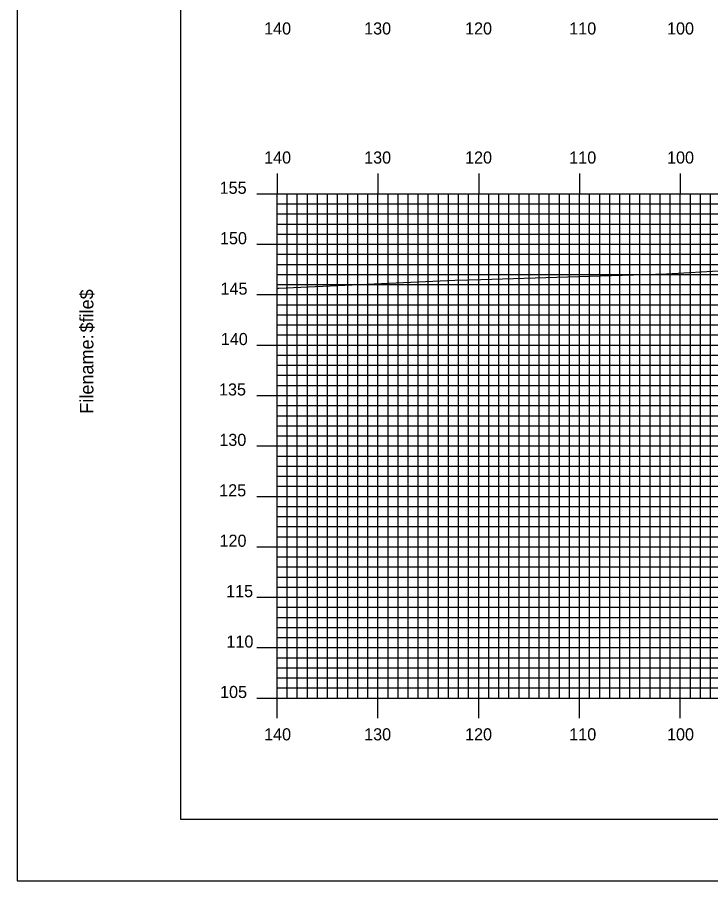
# Model space of a CAD drawing. Extents: x 1769661 to 1770005, y 442591 to 442811.
# Drawn here: x 1769661.2 to 1769730, y 442590.5 to 442676.2 of the extents above; entities that cross this region are included whole.
import ezdxf

# ---------------------------------------------------------------- set-up
doc = ezdxf.new("R2010")
doc.units = 0
for name, color, linetype in [('BORDER', 7, 'Continuous'), ('H_V ANNOTATION', 7, 'Continuous'), ('MAJOR', 7, 'Continuous'), ('MINOR', 7, 'Continuous'), ('PLOT BOUNDARY', 7, 'Continuous'), ('S_Roadway_Centerline', 7, 'Continuous')]:
    doc.layers.add(name, color=color, linetype=linetype)

msp = doc.modelspace()

# ---------------------------------------------------------------- linework, layer by layer
at = {"layer": 'BORDER'}
msp.add_lwpolyline([(1769677.415, 442596.665), (1769997.415, 442596.665), (1769997.415, 442806.665), (1769677.415, 442806.665)], close=True, dxfattribs=at)
at = {"layer": 'MAJOR'}
for p, q in [((1769687.015, 442660.669), (1769687.015, 442658.665)), ((1769697.015, 442660.669), (1769697.015, 442658.665)), ((1769707.015, 442660.669), (1769707.015, 442658.665)), ((1769717.015, 442660.669), (1769717.015, 442658.665)), ((1769727.015, 442660.669), (1769727.015, 442658.665)), ((1769685.011, 442658.665), (1769687.015, 442658.665)), ((1769687.015, 442658.665), (1769967.015, 442658.665)), ((1769687.015, 442608.665), (1769687.015, 442658.665)), ((1769687.015, 442608.665), (1769687.015, 442658.665)), ((1769687.015, 442658.665), (1769967.015, 442658.665)), ((1769697.015, 442608.665), (1769697.015, 442658.665)), ((1769707.015, 442608.665), (1769707.015, 442658.665)), ((1769717.015, 442608.665), (1769717.015, 442658.665)), ((1769727.015, 442608.665), (1769727.015, 442658.665)), ((1769685.011, 442653.665), (1769687.015, 442653.665)), ((1769687.015, 442653.665), (1769967.015, 442653.665)), ((1769685.011, 442648.665), (1769687.015, 442648.665)), ((1769687.015, 442648.665), (1769967.015, 442648.665)), ((1769685.011, 442643.665), (1769687.015, 442643.665)), ((1769687.015, 442643.665), (1769967.015, 442643.665)), ((1769685.011, 442638.665), (1769687.015, 442638.665)), ((1769687.015, 442638.665), (1769967.015, 442638.665)), ((1769685.011, 442633.665), (1769687.015, 442633.665)), ((1769687.015, 442633.665), (1769967.015, 442633.665)), ((1769685.011, 442628.665), (1769687.015, 442628.665)), ((1769687.015, 442628.665), (1769967.015, 442628.665)), ((1769685.011, 442623.665), (1769687.015, 442623.665)), ((1769687.015, 442623.665), (1769967.015, 442623.665)), ((1769685.011, 442618.665), (1769687.015, 442618.665)), ((1769687.015, 442618.665), (1769967.015, 442618.665)), ((1769685.011, 442613.665), (1769687.015, 442613.665)), ((1769687.015, 442613.665), (1769967.015, 442613.665)), ((1769685.011, 442608.665), (1769687.015, 442608.665)), ((1769687.015, 442608.665), (1769967.015, 442608.665)), ((1769687.015, 442608.665), (1769967.015, 442608.665)), ((1769687.015, 442606.661), (1769687.015, 442608.665)), ((1769697.015, 442606.661), (1769697.015, 442608.665)), ((1769707.015, 442606.661), (1769707.015, 442608.665)), ((1769717.015, 442606.661), (1769717.015, 442608.665)), ((1769727.015, 442606.661), (1769727.015, 442608.665))]:
    msp.add_line(p, q, dxfattribs=at)
at = {"layer": 'MINOR'}
for p, q in [((1769688.015, 442608.665), (1769688.015, 442658.665)), ((1769689.015, 442608.665), (1769689.015, 442658.665)), ((1769690.015, 442608.665), (1769690.015, 442658.665)), ((1769691.015, 442608.665), (1769691.015, 442658.665)), ((1769692.015, 442608.665), (1769692.015, 442658.665)), ((1769693.015, 442608.665), (1769693.015, 442658.665)), ((1769694.015, 442608.665), (1769694.015, 442658.665)), ((1769695.015, 442608.665), (1769695.015, 442658.665)), ((1769696.015, 442608.665), (1769696.015, 442658.665)), ((1769698.015, 442608.665), (1769698.015, 442658.665)), ((1769699.015, 442608.665), (1769699.015, 442658.665)), ((1769700.015, 442608.665), (1769700.015, 442658.665)), ((1769701.015, 442608.665), (1769701.015, 442658.665)), ((1769702.015, 442608.665), (1769702.015, 442658.665)), ((1769703.015, 442608.665), (1769703.015, 442658.665)), ((1769704.015, 442608.665), (1769704.015, 442658.665)), ((1769705.015, 442608.665), (1769705.015, 442658.665)), ((1769706.015, 442608.665), (1769706.015, 442658.665)), ((1769708.015, 442608.665), (1769708.015, 442658.665)), ((1769709.015, 442608.665), (1769709.015, 442658.665)), ((1769710.015, 442608.665), (1769710.015, 442658.665)), ((1769711.015, 442608.665), (1769711.015, 442658.665)), ((1769712.015, 442608.665), (1769712.015, 442658.665)), ((1769713.015, 442608.665), (1769713.015, 442658.665)), ((1769714.015, 442608.665), (1769714.015, 442658.665)), ((1769715.015, 442608.665), (1769715.015, 442658.665)), ((1769716.015, 442608.665), (1769716.015, 442658.665)), ((1769718.015, 442608.665), (1769718.015, 442658.665)), ((1769719.015, 442608.665), (1769719.015, 442658.665)), ((1769720.015, 442608.665), (1769720.015, 442658.665)), ((1769721.015, 442608.665), (1769721.015, 442658.665)), ((1769722.015, 442608.665), (1769722.015, 442658.665)), ((1769723.015, 442608.665), (1769723.015, 442658.665)), ((1769724.015, 442608.665), (1769724.015, 442658.665)), ((1769725.015, 442608.665), (1769725.015, 442658.665)), ((1769726.015, 442608.665), (1769726.015, 442658.665)), ((1769728.015, 442608.665), (1769728.015, 442658.665)), ((1769729.015, 442608.665), (1769729.015, 442658.665)), ((1769730.015, 442608.665), (1769730.015, 442658.665)), ((1769687.015, 442657.665), (1769967.015, 442657.665)), ((1769687.015, 442657.665), (1769689.019, 442657.665)), ((1769687.015, 442656.665), (1769967.015, 442656.665)), ((1769687.015, 442656.665), (1769689.019, 442656.665)), ((1769687.015, 442655.665), (1769967.015, 442655.665)), ((1769687.015, 442655.665), (1769689.019, 442655.665)), ((1769687.015, 442654.665), (1769967.015, 442654.665)), ((1769687.015, 442654.665), (1769689.019, 442654.665)), ((1769687.015, 442652.665), (1769967.015, 442652.665)), ((1769687.015, 442652.665), (1769689.019, 442652.665)), ((1769687.015, 442651.665), (1769967.015, 442651.665)), ((1769687.015, 442651.665), (1769689.019, 442651.665)), ((1769687.015, 442650.665), (1769967.015, 442650.665)), ((1769687.015, 442650.665), (1769689.019, 442650.665)), ((1769687.015, 442649.665), (1769967.015, 442649.665)), ((1769687.015, 442649.665), (1769689.019, 442649.665)), ((1769687.015, 442647.665), (1769967.015, 442647.665)), ((1769687.015, 442647.665), (1769689.019, 442647.665)), ((1769687.015, 442646.665), (1769967.015, 442646.665)), ((1769687.015, 442646.665), (1769689.019, 442646.665)), ((1769687.015, 442645.665), (1769967.015, 442645.665)), ((1769687.015, 442645.665), (1769689.019, 442645.665)), ((1769687.015, 442644.665), (1769967.015, 442644.665)), ((1769687.015, 442644.665), (1769689.019, 442644.665)), ((1769687.015, 442642.665), (1769967.015, 442642.665)), ((1769687.015, 442642.665), (1769689.019, 442642.665)), ((1769687.015, 442641.665), (1769967.015, 442641.665)), ((1769687.015, 442641.665), (1769689.019, 442641.665)), ((1769687.015, 442640.665), (1769967.015, 442640.665)), ((1769687.015, 442640.665), (1769689.019, 442640.665)), ((1769687.015, 442639.665), (1769967.015, 442639.665)), ((1769687.015, 442639.665), (1769689.019, 442639.665)), ((1769687.015, 442637.665), (1769967.015, 442637.665)), ((1769687.015, 442637.665), (1769689.019, 442637.665)), ((1769687.015, 442636.665), (1769967.015, 442636.665)), ((1769687.015, 442636.665), (1769689.019, 442636.665)), ((1769687.015, 442635.665), (1769967.015, 442635.665)), ((1769687.015, 442635.665), (1769689.019, 442635.665)), ((1769687.015, 442634.665), (1769967.015, 442634.665)), ((1769687.015, 442634.665), (1769689.019, 442634.665)), ((1769687.015, 442632.665), (1769967.015, 442632.665)), ((1769687.015, 442632.665), (1769689.019, 442632.665)), ((1769687.015, 442631.665), (1769967.015, 442631.665)), ((1769687.015, 442631.665), (1769689.019, 442631.665)), ((1769687.015, 442630.665), (1769967.015, 442630.665)), ((1769687.015, 442630.665), (1769689.019, 442630.665)), ((1769687.015, 442629.665), (1769967.015, 442629.665)), ((1769687.015, 442629.665), (1769689.019, 442629.665)), ((1769687.015, 442627.665), (1769967.015, 442627.665)), ((1769687.015, 442627.665), (1769689.019, 442627.665)), ((1769687.015, 442626.665), (1769967.015, 442626.665)), ((1769687.015, 442626.665), (1769689.019, 442626.665)), ((1769687.015, 442625.665), (1769967.015, 442625.665)), ((1769687.015, 442625.665), (1769689.019, 442625.665)), ((1769687.015, 442624.665), (1769967.015, 442624.665)), ((1769687.015, 442624.665), (1769689.019, 442624.665)), ((1769687.015, 442622.665), (1769967.015, 442622.665)), ((1769687.015, 442622.665), (1769689.019, 442622.665)), ((1769687.015, 442621.665), (1769967.015, 442621.665)), ((1769687.015, 442621.665), (1769689.019, 442621.665)), ((1769687.015, 442620.665), (1769967.015, 442620.665)), ((1769687.015, 442620.665), (1769689.019, 442620.665)), ((1769687.015, 442619.665), (1769967.015, 442619.665)), ((1769687.015, 442619.665), (1769689.019, 442619.665)), ((1769687.015, 442617.665), (1769967.015, 442617.665)), ((1769687.015, 442617.665), (1769689.019, 442617.665)), ((1769687.015, 442616.665), (1769967.015, 442616.665)), ((1769687.015, 442616.665), (1769689.019, 442616.665)), ((1769687.015, 442615.665), (1769967.015, 442615.665)), ((1769687.015, 442615.665), (1769689.019, 442615.665)), ((1769687.015, 442614.665), (1769967.015, 442614.665)), ((1769687.015, 442614.665), (1769689.019, 442614.665)), ((1769687.015, 442612.665), (1769967.015, 442612.665)), ((1769687.015, 442612.665), (1769689.019, 442612.665)), ((1769687.015, 442611.665), (1769967.015, 442611.665)), ((1769687.015, 442611.665), (1769689.019, 442611.665)), ((1769687.015, 442610.665), (1769967.015, 442610.665)), ((1769687.015, 442610.665), (1769689.019, 442610.665)), ((1769687.015, 442609.665), (1769967.015, 442609.665)), ((1769687.015, 442609.665), (1769689.019, 442609.665))]:
    msp.add_line(p, q, dxfattribs=at)
at = {"layer": 'PLOT BOUNDARY'}
msp.add_lwpolyline([(1769661.228, 442590.547), (1770001.228, 442590.547), (1770001.228, 442810.547), (1769661.228, 442810.547)], close=True, dxfattribs=at)
at = {"layer": 'S_Roadway_Centerline'}
msp.add_lwpolyline([(1769687.015, 442649.293), (1769687.167, 442649.298), (1769704.645, 442650.096), (1769707.209, 442650.162), (1769716.906, 442650.478), (1769725.648, 442650.726), (1769731.355, 442651.044), (1769744.901, 442651.762), (1769762.614, 442651.923), (1769763.542, 442651.932), (1769764.174, 442651.952), (1769766.643, 442651.943), (1769783.404, 442652.101), (1769793.271, 442652.323), (1769802.466, 442652.537), (1769810.991, 442652.523), (1769822.479, 442652.429), (1769825.284, 442652.418), (1769840.906, 442652.283), (1769846.533, 442651.967), (1769855.905, 442652.007), (1769858.8, 442652.029)], dxfattribs=at)

# ---------------------------------------------------------------- texts
at = {"layer": 'BORDER'}
for s, p in [('$file$', (1769668.785, 442644.916)), ('Filename:', (1769668.785, 442636.862))]:
    msp.add_text(s, height=1.3392, rotation=90, dxfattribs=at).set_placement(p)
at = {"layer": 'H_V ANNOTATION'}
for s, p in [('140', (1769685.72, 442674.465)), ('130', (1769695.645, 442674.465)), ('120', (1769705.656, 442674.465)), ('110', (1769715.998, 442674.465)), ('100', (1769725.698, 442674.465)), ('140', (1769685.72, 442661.665)), ('130', (1769695.645, 442661.665)), ('120', (1769705.656, 442661.665)), ('110', (1769715.998, 442661.665)), ('100', (1769725.698, 442661.665)), ('155', (1769681.307, 442658.665)), ('150', (1769681.339, 442653.665)), ('145', (1769681.393, 442648.665)), ('140', (1769681.425, 442643.665)), ('135', (1769681.243, 442638.665)), ('130', (1769681.275, 442633.665)), ('125', (1769681.264, 442628.665)), ('120', (1769681.296, 442623.665)), ('115', (1769681.949, 442618.665)), ('110', (1769681.981, 442613.665)), ('105', (1769681.35, 442608.665)), ('140', (1769685.72, 442604.465)), ('130', (1769695.645, 442604.465)), ('120', (1769705.656, 442604.465)), ('110', (1769715.998, 442604.465)), ('100', (1769725.698, 442604.465))]:
    msp.add_text(s, height=1.2, dxfattribs=at).set_placement(p)
at = {"layer": 'MAJOR'}
msp.add_text('-', height=0.012, dxfattribs=at).set_placement((1769687.006, 442608.665))

doc.saveas('drawing.dxf')
